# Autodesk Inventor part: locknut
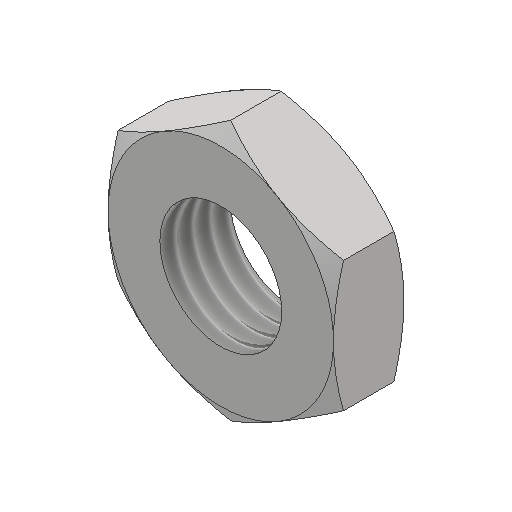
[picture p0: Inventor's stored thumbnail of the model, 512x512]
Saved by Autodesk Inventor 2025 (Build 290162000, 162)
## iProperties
Created: 2016-05
Part Number: locknut
Material: Generic
Document SubType Name: Modeling
Designer: CADCIM
Density: 1 g/cm^3
Appearance: Default
Author: CADCIM
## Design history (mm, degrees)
sketch "Sketch1"
  geometry: L1 (9.6, -5.543)-(0, -11.085); L2 (0, -11.085)-(-9.6, -5.543); L3 (-9.6, -5.543)-(-9.6, 5.543); L4 (-9.6, 5.543)-(0, 11.085); L5 (0, 11.085)-(9.6, 5.543); L6 (9.6, 5.543)-(9.6, -5.543); 2 further points
  constraints: 12 end point, 1 coincident, 1 vertical alignment, 13 other
  dimensions: "d0" = 19.2 distance between parallel lines of L3 L6
extrude "Extrusion1" new body sketch "Sketch1" distance "d1" = 6; taper "d2" = 0 deg
sketch "Sketch2"
  geometry: L1 (0, 11.085)-(-9.6, 5.543) reference; C1 r 9.6 at (0, 0); 1 further point
  constraints: 1 centre point, 1 coincident, 1 tangent
extrude "Extrusion2" sketch "Sketch2" distance "d3" = 10.8; taper "d4" = 60 deg
workplane "Work Plane1"
sketch "Sketch3"
  geometry: L1 (0, -11.085)-(9.6, -5.543) reference; C1 r 9.6 at (0, 0); 1 further point
  constraints: 1 centre point, 1 coincident, 1 tangent
extrude "Extrusion3" sketch "Sketch3" distance "d5" = 10.8; taper "d6" = 60 deg
hole "Hole1" diameter "d9" = 10.376; stored, may be unused: countersink angle "d13" = 90 deg, drill point angle "d15" = 118 deg; dims "d7" = 10, "d8" = 10, "d10" = 24, "d11" = 4, "d12" = 2, "d14" = 31.3
body "Solid1"
sketch "Sketch4"
  geometry: 1 further point
